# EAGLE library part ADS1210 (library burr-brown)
24-Bit Analog-to-Digital Converter
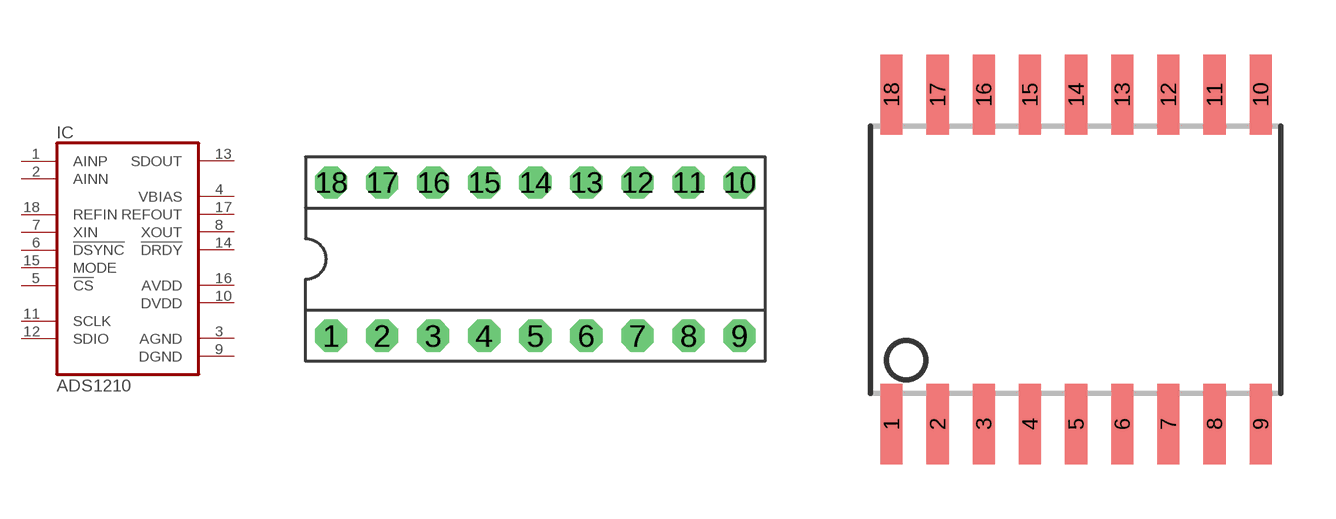
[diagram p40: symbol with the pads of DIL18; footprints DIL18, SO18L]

Designator prefix IC

## ADS1210P (MF: TEXAS INSTRUMENTS; MPN: ADS1210P; OC_FARNELL: 1312336; OC_NEWARK: 96K4580)  [DIL18]
1  AINP  in
2  AINN  in
3  AGND  pwr
4  VBIAS  out
5  !CS  in
6  !DSYNC  in
7  XIN  in
8  XOUT  out
9  DGND  pwr
10  DVDD  pwr
11  SCLK
12  SDIO
13  SDOUT  out
14  !DRDY  out
15  MODE  in
16  AVDD  pwr
17  REFOUT  out
18  REFIN  in

## ADS1210U (MF: TEXAS INSTRUMENTS; MPN: ADS1210U; OC_FARNELL: 1097511; OC_NEWARK: 74K3627)  [SO18L]
Pads as for DIL18

## Footprint DIL18 (pad centres in mm)
Dual In Line
drill 0.813 pad 1.6 octagon: 1 -10.16,-3.81; 2 -7.62,-3.81; 3 -5.08,-3.81; 4 -2.54,-3.81; 5 0,-3.81; 6 2.54,-3.81; 7 5.08,-3.81; 8 7.62,-3.81; 9 10.16,-3.81; 10 10.16,3.81; 11 7.62,3.81; 12 5.08,3.81; 13 2.54,3.81; 14 0,3.81; 15 -2.54,3.81; 16 -5.08,3.81; 17 -7.62,3.81; 18 -10.16,3.81

## Footprint SO18L (pad centres in mm)
Small Outline Package, large
smd 0.61 x 2.21: 1 -5.08,-4.534; 2 -3.81,-4.534; 3 -2.54,-4.534; 4 -1.27,-4.534; 5 0,-4.534; 6 1.27,-4.534; 7 2.54,-4.534; 8 3.81,-4.534; 9 5.08,-4.534; 10 5.08,4.534; 11 3.81,4.534; 12 2.54,4.534; 13 1.27,4.534; 14 0,4.534; 15 -1.27,4.534; 16 -2.54,4.534; 17 -3.81,4.534; 18 -5.08,4.534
